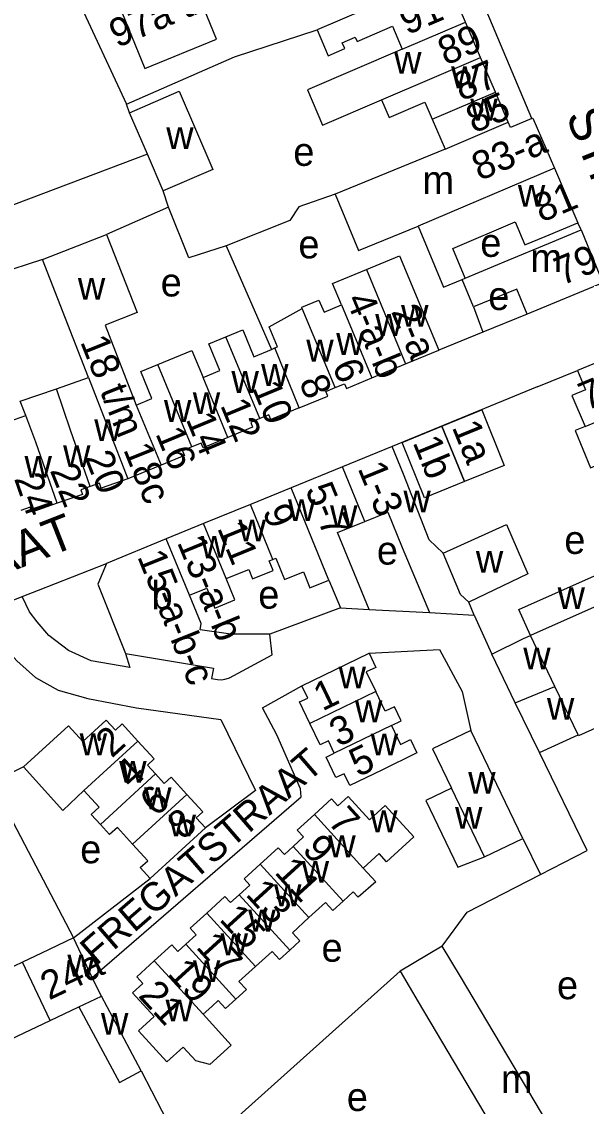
# Model space of a CAD drawing. Extents: x 159261 to 160849, y 382514 to 384534.
# Drawn here: x 159854.6 to 159934.1, y 383277.5 to 383430.4 of the extents above; entities that cross this region are included whole.
import ezdxf

# ---------------------------------------------------------------- set-up
doc = ezdxf.new("R2010")
doc.units = 0
for name, color, linetype in [('BLT_Basislijn', 7, 'Continuous'), ('BLT_Bebouwing', 7, 'Continuous'), ('BLT_Centroide', 7, 'Continuous'), ('BLT_Huisnummer', 7, 'Continuous'), ('BLT_Huisnummer_ tussenligend', 7, 'Continuous'), ('BLT_Huisnummer_reeks', 7, 'Continuous'), ('BLT_Huisnummer_zonder_bebouwing', 7, 'Continuous'), ('BLT_Onderverdeling_panden', 7, 'Continuous'), ('BLT_Plantopo', 7, 'Continuous'), ('BLT_Straatnaam', 7, 'Continuous'), ('BLT_Straatnaam_verkleind', 7, 'Continuous')]:
    doc.layers.add(name, color=color, linetype=linetype)

msp = doc.modelspace()

# ---------------------------------------------------------------- linework, layer by layer
at = {"layer": 'BLT_Basislijn'}
for p, q in [((159858.5, 383441.97), (159869.33, 383418.75)), ((159926.45, 383416.69), (159917.36, 383438.35)), ((159869.75, 383417.51), (159869.33, 383418.75)), ((159875.23, 383404.2), (159874.51, 383406.52)), ((159875.23, 383404.2), (159866.52, 383400.36)), ((159933.41, 383400.99), (159932.94, 383401.98)), ((159883.39, 383398.77), (159889.78, 383384.16)), ((159857.48, 383396.84), (159828.2, 383387.18)), ((159918.23, 383390.14), (159919.57, 383386.59)), ((159925.8, 383389.13), (159919.57, 383386.59)), ((159919.57, 383386.59), (159913.36, 383384.05)), ((159927.22, 383378.9), (159932.92, 383381.16)), ((159927.22, 383378.9), (159906.77, 383370.47)), ((159856.94, 383350.22), (159866.52, 383353.99)), ((159848.93, 383347.07), (159854.64, 383349.32)), ((159854.64, 383349.32), (159856.94, 383350.22)), ((159903.52, 383347.5), (159912.03, 383347.05)), ((159918.32, 383346.71), (159920.8, 383341.19)), ((159888.52, 383333.63), (159894.05, 383336.75)), ((159854.8, 383325.33), (159849.83, 383322.82)), ((159852.29, 383319.55), (159861.86, 383301.19)), ((159925.18, 383315.22), (159927.67, 383310.12)), ((159861.86, 383301.19), (159872.68, 383309.57)), ((159884.28, 383275.3), (159907.88, 383296.49)), ((159871.41, 383282.46), (159877.87, 383269.91))]:
    msp.add_line(p, q, dxfattribs=at)
for points in [[(159869.33, 383418.75), (159884.54, 383425.4), (159896.18, 383429.2)], [(159872.27, 383411.69), (159838.68, 383398.99), (159837.21, 383398.17), (159837.58, 383395.76), (159837.01, 383395.4), (159816.04, 383388.65)], [(159898.74, 383406.04), (159893.6, 383404.26), (159892.33, 383402.32), (159883.39, 383398.77)], [(159883.39, 383398.77), (159878.13, 383397.06), (159875.23, 383404.2)], [(159869.21, 383341.3), (159869.8, 383339.32), (159864.34, 383340.27), (159861.13, 383341.7), (159858.4, 383343.83), (159856.74, 383345.73), (159855.67, 383347.16), (159854.64, 383349.32)], [(159899.47, 383347.72), (159889.52, 383343.99)], [(159848.93, 383347.07), (159851.03, 383343.36), (159853.89, 383340.27), (159856.5, 383337.9), (159859.7, 383336.11), (159863.86, 383334.93), (159870.75, 383333.62), (159882.62, 383331.96), (159887.49, 383321.98), (159880.46, 383316.69)], [(159903.52, 383341.32), (159913.44, 383341.84), (159916.62, 383335.94), (159917.86, 383330.44)], [(159864.51, 383295.6), (159893.94, 383321.1), (159893.86, 383322.22), (159890.53, 383329.82), (159888.52, 383333.63)], [(159927.67, 383310.12), (159934.24, 383313.5)], [(159913.84, 383300.03), (159917.33, 383304.8), (159927.67, 383310.12)]]:
    msp.add_lwpolyline(points, dxfattribs=at)
at = {"layer": 'BLT_Bebouwing'}
for p, q in [((159917.09, 383430.31), (159914.24, 383436.94)), ((159919.23, 383425.31), (159917.09, 383430.31)), ((159921.33, 383420.42), (159919.23, 383425.31)), ((159872.27, 383411.69), (159869.75, 383417.51)), ((159912.43, 383416.61), (159914.24, 383412.39)), ((159874.51, 383406.52), (159872.27, 383411.69)), ((159929.64, 383409.69), (159932.94, 383401.98)), ((159857.48, 383396.84), (159866.52, 383400.36)), ((159863.96, 383380.19), (159857.48, 383396.84)), ((159908.65, 383382.1), (159913.36, 383384.05)), ((159903.91, 383380.14), (159908.65, 383382.1)), ((159859.47, 383378.62), (159863.96, 383380.19)), ((159933.96, 383373.3), (159943.32, 383377.11)), ((159850.33, 383373.15), (159855.13, 383374.83)), ((159906.77, 383370.47), (159899.78, 383367.61)), ((159899.78, 383367.61), (159892.53, 383364.64)), ((159892.53, 383364.64), (159886.8, 383362.3)), ((159886.8, 383362.3), (159880.19, 383359.59)), ((159880.19, 383359.59), (159874.94, 383357.44)), ((159874.94, 383357.44), (159866.52, 383353.99)), ((159913.98, 383355.41), (159911.99, 383357.29)), ((159918.32, 383346.71), (159917.56, 383348.53)), ((159912.03, 383347.05), (159918.32, 383346.71)), ((159869.21, 383341.3), (159879.03, 383339.65)), ((159894.05, 383336.75), (159903.52, 383341.32)), ((159924.13, 383334.31), (159920.8, 383341.19)), ((159932.99, 383329.82), (159929.71, 383336.63)), ((159927.53, 383327.31), (159924.13, 383334.31)), ((159861.14, 383331.09), (159854.8, 383325.33)), ((159925.18, 383315.22), (159917.86, 383330.44)), ((159934.24, 383313.5), (159927.53, 383327.31)), ((159872.68, 383309.57), (159880.46, 383316.69)), ((159864.51, 383295.6), (159861.86, 383301.19)), ((159913.84, 383300.03), (159907.88, 383296.49)), ((159854.65, 383297.77), (159824.17, 383283.32)), ((159871.41, 383282.46), (159865.82, 383293)), ((159858.55, 383289.55), (159862.62, 383291.48)), ((159828.07, 383275.1), (159858.55, 383289.55))]:
    msp.add_line(p, q, dxfattribs=at)
for points in [[(159914.24, 383436.94), (159909.65, 383434.97), (159896.18, 383429.2)], [(159896.18, 383429.2), (159897.74, 383425.56), (159900.09, 383426.57), (159899.74, 383427.38), (159901.56, 383428.16), (159901.82, 383427.57), (159906.82, 383429.71), (159908.2, 383426.5)], [(159908.2, 383426.5), (159894.82, 383420.76), (159896.96, 383415.78), (159905.29, 383419.33)], [(159869.75, 383417.51), (159876.75, 383420.54), (159881.5, 383409.54), (159874.51, 383406.52)], [(159905.29, 383419.33), (159906.34, 383416.86), (159911.4, 383419.03), (159912.43, 383416.61)], [(159923.14, 383416.2), (159921.33, 383420.42)], [(159914.24, 383412.39), (159918.54, 383414.23), (159923.14, 383416.2)], [(159926.45, 383416.69), (159923.47, 383415.42), (159923.14, 383416.2)], [(159926.45, 383416.69), (159926.6, 383416.76), (159929.64, 383409.69)], [(159914.24, 383412.39), (159898.74, 383406.04)], [(159898.74, 383406.04), (159902.05, 383398.09), (159910.46, 383401.53)], [(159910.46, 383401.53), (159914.02, 383392.95), (159916.62, 383394)], [(159917.06, 383394.18), (159915.33, 383398.37), (159924.09, 383402.13), (159925.48, 383398.88), (159928.32, 383400.06), (159932.94, 383401.98)], [(159917.06, 383394.18), (159923.11, 383396.72), (159928.79, 383399.07), (159933.41, 383400.99)], [(159933.41, 383400.99), (159936.49, 383393.56), (159925.8, 383389.13)], [(159866.52, 383400.36), (159870.81, 383389.34), (159866.3, 383387.58), (159870.69, 383376.3)], [(159903.14, 383395.42), (159907.83, 383397.37), (159913.36, 383384.05)], [(159899.64, 383390.43), (159898.38, 383393.43), (159903.14, 383395.42)], [(159918.23, 383390.14), (159916.62, 383394)], [(159925.8, 383389.13), (159924.33, 383392.67), (159918.23, 383390.14)], [(159894.11, 383389.94), (159894.04, 383390.11), (159896.46, 383391.11), (159897.17, 383389.41), (159899.64, 383390.43)], [(159890.24, 383384.36), (159890.62, 383384.51), (159889.44, 383387.35), (159894.11, 383389.94)], [(159880.12, 383380.19), (159882.5, 383381.18), (159880.94, 383384.93), (159883.34, 383385.93)], [(159883.34, 383385.93), (159885.73, 383386.92), (159887.29, 383383.13), (159889.78, 383384.16)], [(159873.73, 383382.02), (159876.16, 383383.02), (159878.54, 383384.01), (159880.12, 383380.19)], [(159889.78, 383384.16), (159890.24, 383384.36)], [(159893.68, 383375.94), (159890.24, 383384.36)], [(159943.32, 383377.11), (159940.32, 383384.26), (159932.92, 383381.16)], [(159870.69, 383376.3), (159872.92, 383377.23), (159871.35, 383381.03), (159873.73, 383382.02)], [(159932.92, 383381.16), (159934.04, 383378.48), (159932.12, 383377.67), (159933.96, 383373.3)], [(159898.74, 383378.78), (159900.05, 383379.32), (159900.33, 383378.65), (159903.91, 383380.14)], [(159855.13, 383374.83), (159854.36, 383376.84), (159859.47, 383378.62)], [(159893.68, 383375.94), (159897.7, 383377.57), (159897.43, 383378.24), (159898.74, 383378.78)], [(159856.57, 383371.07), (159855.13, 383374.83)], [(159893.68, 383375.94), (159889.68, 383374.28), (159889.41, 383374.93), (159888.12, 383374.4)], [(159888.12, 383374.4), (159886.83, 383373.86), (159887.11, 383373.2), (159883.62, 383371.75)], [(159933.96, 383373.3), (159932.56, 383372.71), (159934.75, 383367.48), (159938.07, 383368.87), (159938.88, 383366.95)], [(159883.62, 383371.75), (159880.13, 383370.3), (159879.86, 383370.96), (159878.54, 383370.41)], [(159878.54, 383370.41), (159877.21, 383369.86), (159877.48, 383369.2), (159874.2, 383367.84)], [(159911.99, 383357.29), (159908.38, 383366.55), (159906.77, 383370.47)], [(159874.2, 383367.84), (159869.53, 383365.9)], [(159869.53, 383365.9), (159865.77, 383364.6), (159865.54, 383365.28), (159864.22, 383364.82)], [(159864.22, 383364.82), (159862.9, 383364.36), (159863.13, 383363.7), (159859.56, 383362.46)], [(159859.56, 383362.46), (159855.99, 383361.22), (159855.76, 383361.9), (159854.41, 383361.43)], [(159902.94, 383359.91), (159906.15, 383361.22), (159908.2, 383356.23), (159912.03, 383347.05)], [(159903.52, 383347.5), (159899.08, 383358.33), (159902.94, 383359.91)], [(159913.98, 383355.41), (159922.87, 383359.49), (159925.88, 383352.5), (159917.56, 383348.53)], [(159866.52, 383353.99), (159865.29, 383351.05), (159869.21, 383341.3)], [(159883.36, 383351.84), (159886.56, 383353.15), (159887.11, 383351.79), (159890.02, 383352.98), (159889.46, 383354.35), (159889.97, 383354.56)], [(159889.97, 383354.56), (159890.36, 383354.72), (159891.59, 383351.71), (159894.26, 383352.81), (159895.19, 383350.54), (159897.86, 383351.64)], [(159878.19, 383349.5), (159880.64, 383350.5), (159881.79, 383347.69), (159884.59, 383348.84), (159883.36, 383351.84)], [(159897.86, 383351.64), (159899.47, 383347.72)], [(159879.71, 383344.61), (159879.83, 383345.51), (159878.19, 383349.5)], [(159899.47, 383347.72), (159903.52, 383347.5)], [(159889.52, 383343.99), (159884.02, 383344.03), (159879.71, 383344.61)], [(159883.83, 383337.84), (159889.84, 383341.08), (159889.52, 383343.99)], [(159920.8, 383341.19), (159925.3, 383343.38), (159926.25, 383343.84)], [(159929.71, 383336.63), (159926.25, 383343.84)], [(159903.52, 383341.32), (159904.48, 383339.33), (159903.12, 383338.68), (159904.45, 383335.92)], [(159879.03, 383339.65), (159881.6, 383339.22), (159881.33, 383337.76), (159882.17, 383337.6)], [(159882.17, 383337.6), (159882.7, 383337.59), (159883.21, 383337.65), (159883.71, 383337.8), (159883.83, 383337.84)], [(159895.17, 383331.44), (159893.72, 383334.45), (159894.89, 383335.01), (159894.05, 383336.75)], [(159906.68, 383331.14), (159908.04, 383331.8), (159907.08, 383333.79), (159905.78, 383333.16), (159904.45, 383335.92)], [(159944.84, 383335.23), (159939.54, 383332.83), (159939.63, 383332.63), (159933.06, 383329.66), (159932.99, 383329.82)], [(159870.94, 383328.95), (159868.73, 383331.36), (159867.77, 383330.48), (159866.48, 383331.89), (159863.17, 383328.87), (159861.14, 383331.09)], [(159898.62, 383327.25), (159897.78, 383328.99), (159896.62, 383328.43), (159895.17, 383331.44)], [(159906.68, 383331.14), (159907.96, 383328.47), (159909.36, 383329.15), (159910.27, 383327.26), (159905.3, 383324.86), (159900.8, 383322.69)], [(159917.86, 383330.44), (159912.47, 383327.85), (159915.14, 383322.3)], [(159873.43, 383324.3), (159872.28, 383325.55), (159873.24, 383326.43), (159870.94, 383328.95)], [(159900.8, 383322.69), (159900, 383324.34), (159898.85, 383323.79), (159897.45, 383326.69), (159898.62, 383327.25)], [(159854.8, 383325.33), (159860.35, 383319.16), (159863.32, 383321.98)], [(159877.85, 383321.42), (159875.64, 383323.83), (159874.66, 383322.94), (159873.43, 383324.3)], [(159865.65, 383317.19), (159864.35, 383318.61), (159865.46, 383319.63), (159863.32, 383321.98)], [(159880.46, 383316.69), (159879.17, 383318.1), (159880.1, 383318.95), (159877.85, 383321.42)], [(159915.14, 383322.3), (159911.5, 383320.55), (159916.01, 383311.17), (159919.79, 383312.63)], [(159895.82, 383318.6), (159898.23, 383320.8), (159899.11, 383319.83), (159900.57, 383321.15)], [(159900.57, 383321.15), (159903.58, 383317.85), (159905.79, 383319.86), (159909.82, 383315.44), (159905.97, 383311.93), (159904.93, 383313.07), (159902.71, 383311.04)], [(159892.82, 383314.09), (159894.29, 383315.42), (159893.4, 383316.4), (159895.82, 383318.6)], [(159870.19, 383314.42), (159868.05, 383316.77), (159866.95, 383315.76), (159865.65, 383317.19)], [(159919.79, 383312.63), (159925.18, 383315.22)], [(159872.68, 383309.57), (159871.27, 383311.1), (159872.34, 383312.07), (159870.19, 383314.42)], [(159888.17, 383311.59), (159890.72, 383313.91), (159891.59, 383312.96), (159892.82, 383314.09)], [(159885.21, 383307.27), (159886.69, 383308.62), (159885.89, 383309.51), (159888.17, 383311.59)], [(159902.71, 383311.04), (159904.46, 383309.12), (159901.99, 383306.92), (159901.29, 383307.69), (159899.85, 383306.38)], [(159880.65, 383304.7), (159883.21, 383307.04), (159884, 383306.17), (159885.21, 383307.27)], [(159899.85, 383306.38), (159898.4, 383305.07), (159897.38, 383306.19), (159895.05, 383304.06)], [(159877.68, 383300.32), (159879.13, 383301.64), (159878.29, 383302.56), (159880.65, 383304.7)], [(159895.05, 383304.06), (159892.71, 383301.93), (159893.77, 383300.76), (159892.33, 383299.45)], [(159861.86, 383301.19), (159857.34, 383299.05), (159854.65, 383297.77)], [(159873.25, 383297.95), (159875.71, 383300.2), (159876.54, 383299.28), (159877.68, 383300.32)], [(159936.26, 383261.89), (159931.45, 383268.36), (159932.29, 383269), (159929.73, 383273.29), (159916.39, 383295.73), (159913.84, 383300.03)], [(159892.33, 383299.45), (159890.89, 383298.14), (159889.84, 383299.29), (159887.51, 383297.17)], [(159880.12, 383290.42), (159884.08, 383286.09), (159881.08, 383283.35), (159879.09, 383283.85), (159877.31, 383285.8), (159875.02, 383283.71), (159871.01, 383288.11), (159873.21, 383290.12), (159870.18, 383293.44), (159871.65, 383294.77), (159870.79, 383295.71), (159873.25, 383297.95)], [(159887.51, 383297.17), (159885.18, 383295.05), (159886.23, 383293.9), (159884.76, 383292.56)], [(159865.82, 383293), (159865.02, 383294.52), (159864.51, 383295.6)], [(159907.88, 383296.49), (159910.43, 383292.19), (159923.9, 383269.54), (159922.33, 383268.34), (159925.46, 383264.06)], [(159884.76, 383292.56), (159883.29, 383291.22), (159882.25, 383292.36), (159881.34, 383291.52), (159880.12, 383290.42)], [(159862.62, 383291.48), (159868.33, 383280.8), (159871.41, 383282.46)]]:
    msp.add_lwpolyline(points, dxfattribs=at)
msp.add_lwpolyline([(159926.25, 383343.84), (159924.65, 383347.48), (159936.99, 383352.97), (159938.61, 383349.34)], close=True, dxfattribs=at)
at = {"layer": 'BLT_Onderverdeling_panden'}
for p, q in [((159908.2, 383426.5), (159917.09, 383430.31)), ((159905.29, 383419.33), (159919.23, 383425.31)), ((159912.43, 383416.61), (159921.33, 383420.42)), ((159929.64, 383409.69), (159910.46, 383401.53)), ((159903.14, 383395.42), (159908.65, 383382.1)), ((159899.64, 383390.43), (159903.91, 383380.14)), ((159898.74, 383378.78), (159894.11, 383389.94)), ((159888.12, 383374.4), (159883.34, 383385.93)), ((159878.54, 383370.41), (159873.73, 383382.02)), ((159863.96, 383380.19), (159869.53, 383365.9)), ((159883.62, 383371.75), (159880.12, 383380.19)), ((159870.69, 383376.3), (159874.2, 383367.84)), ((159859.56, 383362.46), (159856.57, 383371.07)), ((159902.94, 383359.91), (159899.78, 383367.61)), ((159897.86, 383351.64), (159892.53, 383364.64)), ((159889.97, 383354.56), (159886.8, 383362.3)), ((159883.36, 383351.84), (159880.19, 383359.59)), ((159878.19, 383349.5), (159874.94, 383357.44)), ((159924.13, 383334.31), (159929.71, 383336.63)), ((159904.45, 383335.92), (159895.17, 383331.44)), ((159906.68, 383331.14), (159898.62, 383327.25)), ((159863.32, 383321.98), (159870.94, 383328.95)), ((159927.53, 383327.31), (159932.99, 383329.82)), ((159865.65, 383317.19), (159873.43, 383324.3)), ((159870.19, 383314.42), (159877.85, 383321.42)), ((159919.79, 383312.63), (159915.14, 383322.3)), ((159895.82, 383318.6), (159902.71, 383311.04)), ((159899.85, 383306.38), (159892.82, 383314.09)), ((159895.05, 383304.06), (159888.17, 383311.59)), ((159892.33, 383299.45), (159885.21, 383307.27)), ((159887.51, 383297.17), (159880.65, 383304.7)), ((159884.76, 383292.56), (159877.68, 383300.32)), ((159858.55, 383289.55), (159854.65, 383297.77)), ((159880.12, 383290.42), (159873.25, 383297.95)), ((159862.62, 383291.48), (159865.82, 383293))]:
    msp.add_line(p, q, dxfattribs=at)
for points in [[(159916.62, 383394), (159917.06, 383394.18)], [(159864.22, 383364.82), (159861.42, 383372.75), (159859.47, 383378.62)], [(159917.56, 383348.53), (159916.4, 383349.62), (159913.98, 383355.41)]]:
    msp.add_lwpolyline(points, dxfattribs=at)
at = {"layer": 'BLT_Plantopo'}
for points in [[(159873.75, 383448.18), (159863.62, 383444.06), (159871.89, 383423.76), (159882.01, 383427.88)], [(159916.98, 383365.55), (159913.79, 383373.32), (159919.41, 383375.64), (159922.58, 383367.77)], [(159913.79, 383373.32), (159916.98, 383365.55), (159911.32, 383363.22), (159908.18, 383371.01)]]:
    msp.add_lwpolyline(points, close=True, dxfattribs=at)

# ---------------------------------------------------------------- texts
at = {"layer": 'BLT_Centroide'}
for s, p in [('w', (159907.05, 383423.03)), ('w', (159915.09, 383420.97)), ('w', (159917.78, 383416.41)), ('w', (159874.93, 383412.41)), ('e', (159892.84, 383410.03)), ('m', (159911.04, 383406.06)), ('w', (159924.49, 383404.28)), ('e', (159893.56, 383396.99)), ('e', (159919.2, 383397.2)), ('m', (159926.27, 383395.06)), ('e', (159874.15, 383391.62)), ('w', (159862.47, 383391.16)), ('e', (159920.32, 383389.71)), ('w', (159908.03, 383387.34)), ('w', (159904.39, 383386.06)), ('w', (159894.67, 383382.45)), ('w', (159898.89, 383383.38)), ('w', (159884.12, 383378.02)), ('w', (159888.3, 383379.02)), ('w', (159878.67, 383375.03)), ('w', (159874.61, 383373.94)), ('w', (159864.78, 383371.23)), ('w', (159860.39, 383367.58)), ('w', (159854.95, 383366.06)), ('w', (159908.36, 383361.19)), ('w', (159892.08, 383359.95)), ('w', (159898.02, 383359.08)), ('w', (159885.11, 383357.08)), ('e', (159931.04, 383355.32)), ('w', (159879.77, 383354.78)), ('e', (159904.62, 383353.82)), ('w', (159918.57, 383352.68)), ('b', (159872.86, 383347.5)), ('e', (159887.9, 383347.61)), ('w', (159930.09, 383347.56)), ('w', (159925.25, 383339.06)), ('w', (159899.22, 383336.38)), ('w', (159928.59, 383331.95)), ('w', (159901.53, 383331.59)), ('w', (159862.73, 383326.94)), ('w', (159903.74, 383326.91)), ('w', (159868.29, 383323.06)), ('w', (159917.49, 383321.53)), ('w', (159871.81, 383319.34)), ('w', (159915.64, 383316.59)), ('w', (159875.26, 383315.5)), ('w', (159903.66, 383316.09)), ('w', (159897.77, 383312.56)), ('e', (159862.8, 383311.71)), ('w', (159894.02, 383308.98)), ('w', (159890.12, 383305.66)), ('w', (159886.48, 383302.08)), ('w', (159882.59, 383298.75)), ('e', (159896.82, 383297.83)), ('w', (159861, 383295.75)), ('w', (159878.69, 383294.97)), ('e', (159930.01, 383292.55)), ('w', (159874.83, 383289.42)), ('w', (159865.73, 383287.53)), ('m', (159922.11, 383279.33)), ('e', (159900.38, 383276.79))]:
    msp.add_text(s, height=4, dxfattribs=at).set_placement(p)
at = {"layer": 'BLT_Huisnummer'}
for s, rotation, p in [('89', 23.2095, (159914.32, 383424.13)), ('85', 23.2115, (159918.29, 383414.57)), ('81', 22.5079, (159927.78, 383402)), ('79', 22.5113, (159930.68, 383393.11)), ('6', 292.5168, (159898.27, 383381.85)), ('10', 292.5072, (159886.98, 383378.76)), ('14', 292.5203, (159877.64, 383374.34)), ('24', 289.1542, (159853.45, 383365.96)), ('9', 292.2768, (159888.45, 383361.38)), ('1', 25.7565, (159896.93, 383333.1)), ('2', 42.4488, (159867.26, 383326.45)), ('5', 25.7529, (159901.97, 383323.81)), ('7', 312.3557, (159897.56, 383317.46)), ('8', 42.4337, (159877.33, 383314.86)), ('11', 312.3421, (159890.06, 383310.36)), ('15', 312.3504, (159882.29, 383303.73)), ('24a', 25.3723, (159858.42, 383292.36)), ('21', 312.3572, (159870.86, 383292.98))]:
    msp.add_text(s, height=4, rotation=rotation, dxfattribs=at).set_placement(p)
at = {"layer": 'BLT_Huisnummer_ tussenligend'}
for s, rotation, p in [('87', 23.2188, (159916.52, 383419.09)), ('8', 292.5168, (159893.6, 383379.6)), ('12', 292.5072, (159882.5, 383376.3)), ('16', 292.5203, (159873.36, 383372.3)), ('20', 291.8284, (159863.37, 383368.96)), ('22', 291.8284, (159858.49, 383367.11)), ('11', 292.2813, (159882.07, 383358.99)), ('3', 25.7565, (159899.18, 383328.06)), ('4', 42.4488, (159870.06, 383322.06)), ('6', 42.4488, (159873.5, 383318.15)), ('9', 312.3557, (159893.96, 383313.54)), ('13', 312.3421, (159886, 383307.25)), ('17', 312.3504, (159879, 383299.82)), ('19', 312.3504, (159874.94, 383296.06))]:
    msp.add_text(s, height=4, rotation=rotation, dxfattribs=at).set_placement(p)
at = {"layer": 'BLT_Huisnummer_reeks'}
for s, rotation, p in [('91-93', 23.209, (159908.87, 383428.43)), ('83-a', 23.211, (159919.1, 383407.87)), ('4-a-b', 292.5036, (159900.19, 383391.22)), ('2-a', 292.5036, (159906.58, 383389.52)), ('18 t/m 18c', 291.8284, (159862.76, 383385.24)), ('77-a', 22.7593, (159934.13, 383375.46)), ('1-3', 292.2652, (159901.87, 383367.41)), ('5-7', 292.2652, (159894.46, 383364.41)), ('13-a-b', 292.2718, (159876.41, 383356.97)), ('15-a-b-c', 291.9047, (159870.8, 383354.97))]:
    msp.add_text(s, height=4, rotation=rotation, dxfattribs=at).set_placement(p)
at = {"layer": 'BLT_Huisnummer_zonder_bebouwing'}
for s, rotation, p in [('97a t/m h', 23.209, (159868, 383426.62)), ('1a', 292.2768, (159915.15, 383373.21)), ('1b', 292.2768, (159909.62, 383371.05))]:
    msp.add_text(s, height=4, rotation=rotation, dxfattribs=at).set_placement(p)
at = {"layer": 'BLT_Straatnaam'}
for s, rotation, p in [('STRIJPSESTRAAT', 291.9474, (159931.21, 383417.1)), ('KERKAKKERSTRAAT', 21.4486, (159799.9, 383331.9))]:
    msp.add_text(s, height=5, rotation=rotation, dxfattribs=at).set_placement(p)
at = {"layer": 'BLT_Straatnaam_verkleind'}
msp.add_text('FREGATSTRAAT', height=4, rotation=40.9058, dxfattribs=at).set_placement((159865, 383297.17))

doc.saveas('drawing.dxf')
